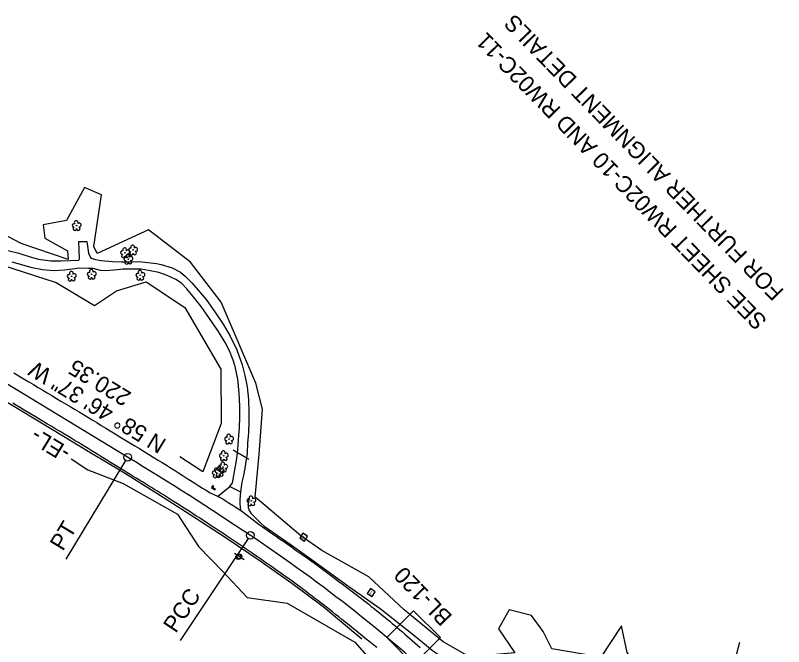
# Model space of a CAD drawing. Extents: x 473158 to 477500, y 500738 to 505114.
# Drawn here: x 474989 to 475741, y 502724 to 503341 of the extents above; entities that cross this region are included whole.
import ezdxf

# ---------------------------------------------------------------- set-up
doc = ezdxf.new("R2010")
doc.units = 0
for name, color, linetype in [('CTL Secondary Horizontal and Vertical CELL', 7, 'Continuous'), ('CTL Secondary Horizontal and Vertical Text', 7, 'Continuous'), ('CTL Sheet Notes CELL', 7, 'Continuous'), ('Exist Guardrail', 7, 'Continuous'), ('Exist Horizontal Alignment', 7, 'Continuous'), ('Exist Horizontal Alignment Direction Label', 7, 'Continuous'), ('Exist Other Culture Gate', 7, 'Continuous'), ('Exist Roads EOP', 7, 'Continuous'), ('Exist Roads EOP Other', 7, 'Continuous'), ('Exist Roads Soil', 7, 'Continuous'), ('Exist Structure Minor Head and End Wall', 7, 'Continuous'), ('Exist Utilities Other Pole CELL', 7, 'Continuous'), ('Exist Utilities Telephone Pedestal CELL', 7, 'Continuous'), ('Exist Utilities Telephone Pole CELL', 7, 'Continuous'), ('Exist Vegetation Tree CELL', 7, 'Continuous'), ('Exist Vegetation Woods Line', 7, 'Continuous')]:
    doc.layers.add(name, color=color, linetype=linetype)

msp = doc.modelspace()

# ---------------------------------------------------------------- linework, layer by layer
at = {"layer": 'CTL Secondary Horizontal and Vertical CELL'}
msp.add_line((475378.34, 502732.63), (475378.34, 502732.63), dxfattribs=at)
msp.add_lwpolyline([(475352.26, 502732.72), (475378.47, 502758.92), (475404.72, 502732.67), (475378.52, 502706.47)], close=True, dxfattribs=at)
at = {"layer": 'Exist Guardrail'}
for points in [[(475115.79, 502880.86), (475093.81, 502894.53), (475063.36, 502912.74), (475035.88, 502929.45), (475010.91, 502944.41), (474990.4, 502956.68), (474968.08, 502970.09), (474943.75, 502984.87), (474916.99, 503000.7), (474891.57, 503015.94), (474864.64, 503032.77), (474837.82, 503050.6), (474809.48, 503069.89), (474784.69, 503087.26), (474764.25, 503101.88), (474737.05, 503123.11), (474718.63, 503138.15), (474703.33, 503150.95), (474689.31, 503162.58), (474683.03, 503166.54), (474677.9, 503167.41)], [(475327.84, 502731.26), (475289.95, 502762.7), (475259.47, 502785.5), (475228.43, 502807.52), (475194.97, 502829.87), (475164.5, 502849.96), (475133.52, 502869.78), (475115.79, 502880.86)], [(475217.33, 502867.76), (475216.44, 502862.82), (475216.67, 502859.88), (475217.59, 502857.13), (475219.31, 502854.45), (475221.83, 502851.72), (475229.36, 502844.29), (475232.25, 502841.82), (475257.72, 502824.07), (475280.52, 502807.76), (475315.04, 502782.65), (475345.62, 502761.25), (475378.34, 502735.51), (475396.81, 502720.46), (475415.24, 502707), (475419.92, 502704.07), (475423.92, 502701.99), (475431.54, 502699.97), (475438.09, 502699.45), (475447.54, 502700.48), (475462.27, 502702.99), (475484.79, 502708.35), (475503.22, 502713.19)]]:
    msp.add_lwpolyline(points, dxfattribs=at)
at = {"layer": 'Exist Horizontal Alignment'}
for p, q in [((475098.63, 502909.13), (474910.19, 503023.36)), ((475096.69, 502905.93), (475038.25, 502809.53)), ((475216.71, 502829.51), (475150.03, 502729.7))]:
    msp.add_line(p, q, dxfattribs=at)
for centre in [(475098.63, 502909.13), (475218.79, 502832.63)]:
    msp.add_circle(centre, 3.75, dxfattribs=at)
for centre, radius, start, end in [((473422.15, 500143.44), 3234.14, 56.25321, 58.77708), ((474341.25, 501519.13), 1579.67, 47.05976, 56.25321)]:
    msp.add_arc(centre, radius, start, end, dxfattribs=at)
at = {"layer": 'Exist Other Culture Gate'}
msp.add_line((475217.28, 502907.02), (475201.99, 502915.99), dxfattribs=at)
at = {"layer": 'Exist Roads EOP'}
for points in [[(474987.32, 502991.6), (474990.65, 502989.58), (474994.12, 502987.49), (474997.91, 502985.21), (475002.02, 502982.76), (475006.44, 502980.12), (475011.01, 502977.41), (475015.54, 502974.71), (475020.03, 502972.03), (475024.48, 502969.37), (475028.91, 502966.72), (475033.35, 502964.06), (475037.79, 502961.4), (475042.25, 502958.74), (475046.68, 502956.08), (475051.08, 502953.44), (475055.43, 502950.81), (475059.75, 502948.2), (475064.05, 502945.58), (475068.39, 502942.95), (475072.76, 502940.29), (475077.17, 502937.62), (475081.65, 502934.9), (475086.27, 502932.09), (475091.01, 502929.22), (475095.87, 502926.26), (475100.75, 502923.3), (475105.51, 502920.4), (475110.15, 502917.56), (475114.68, 502914.78), (475119.14, 502912.05), (475123.56, 502909.34), (475127.94, 502906.64), (475132.28, 502903.97), (475136.53, 502901.35), (475140.62, 502898.81), (475144.55, 502896.34), (475148.32, 502893.95), (475152.09, 502891.56), (475156.01, 502889.06), (475160.08, 502886.47), (475164.31, 502883.77), (475168.36, 502881.2), (475171.91, 502878.99), (475174.95, 502877.13), (475179.54, 502874.43), (475182.3, 502872.88), (475187.13, 502870.72), (475191.66, 502868.39), (475194.11, 502866.87), (475196.95, 502864.99), (475201.9, 502861.84), (475203.85, 502860.64), (475208.93, 502857.47), (475213.05, 502854.51), (475215.96, 502852.2), (475220.03, 502848.88), (475224.63, 502845.43), (475227.48, 502843.34), (475230.27, 502841.31), (475233.01, 502839.35), (475235.7, 502837.47), (475238.42, 502835.58), (475241.27, 502833.6), (475244.25, 502831.55), (475247.37, 502829.42), (475250.45, 502827.31), (475253.33, 502825.32), (475256.03, 502823.44), (475258.53, 502821.68), (475261.03, 502819.92), (475263.69, 502818.04), (475266.52, 502816.04), (475269.52, 502813.92), (475272.58, 502811.76), (475275.57, 502809.64), (475278.5, 502807.55), (475281.36, 502805.51), (475284.15, 502803.5), (475286.85, 502801.53), (475289.46, 502799.59), (475291.98, 502797.7), (475294.52, 502795.78), (475297.17, 502793.77), (475299.93, 502791.69), (475302.8, 502789.52), (475305.72, 502787.32), (475308.62, 502785.14), (475311.49, 502782.99), (475314.35, 502780.86), (475317.13, 502778.78), (475319.78, 502776.77), (475322.3, 502774.85), (475324.69, 502772.99), (475327.05, 502771.15), (475329.48, 502769.25), (475331.97, 502767.29), (475334.52, 502765.27), (475337.12, 502763.21), (475339.74, 502761.13), (475342.38, 502759.03), (475345.04, 502756.9), (475347.68, 502754.78), (475350.25, 502752.7), (475352.77, 502750.66), (475355.22, 502748.65), (475357.64, 502746.64), (475360.09, 502744.59), (475362.55, 502742.49), (475365.02, 502740.36), (475367.49, 502738.21), (475369.93, 502736.09), (475372.34, 502733.99), (475374.72, 502731.91), (475377.14, 502729.81), (475379.67, 502727.64), (475382.29, 502725.41), (475385.02, 502723.12)], [(475342.53, 502722.84), (475339.47, 502725.33), (475336.39, 502727.82), (475333.41, 502730.24), (475330.53, 502732.58), (475327.74, 502734.83), (475325.01, 502737.04), (475322.3, 502739.22), (475319.6, 502741.38), (475316.91, 502743.53), (475314.17, 502745.72), (475311.31, 502748), (475308.33, 502750.39), (475305.22, 502752.88), (475302.09, 502755.37), (475299.04, 502757.79), (475296.08, 502760.13), (475293.2, 502762.38), (475290.37, 502764.59), (475287.55, 502766.77), (475284.73, 502768.92), (475281.93, 502771.06), (475279.14, 502773.17), (475276.38, 502775.26), (475273.64, 502777.34), (475270.92, 502779.4), (475268.31, 502781.37), (475263.68, 502784.83), (475259.62, 502787.78), (475255.06, 502791.06), (475252.52, 502792.87), (475249.89, 502794.73), (475247.25, 502796.6), (475244.6, 502798.48), (475241.95, 502800.35), (475239.29, 502802.22), (475236.62, 502804.09), (475233.94, 502805.96), (475231.24, 502807.82), (475228.54, 502809.68), (475225.83, 502811.54), (475223.11, 502813.41), (475220.38, 502815.27), (475217.61, 502817.16), (475214.79, 502819.09), (475211.91, 502821.07), (475208.98, 502823.09), (475206.03, 502825.11), (475203.12, 502827.1), (475200.24, 502829.04), (475197.41, 502830.95), (475194.56, 502832.85), (475191.64, 502834.79), (475188.65, 502836.77), (475185.59, 502838.79), (475182.45, 502840.85), (475179.19, 502842.98), (475175.83, 502845.17), (475172.36, 502847.42), (475168.87, 502849.68), (475165.43, 502851.91), (475162.05, 502854.09), (475158.72, 502856.23), (475155.43, 502858.34), (475152.17, 502860.43), (475148.94, 502862.5), (475145.74, 502864.55), (475142.59, 502866.56), (475139.52, 502868.52), (475136.53, 502870.41), (475133.62, 502872.25), (475130.75, 502874.06), (475127.85, 502875.87), (475124.93, 502877.68), (475121.99, 502879.48), (475119.03, 502881.29), (475116.07, 502883.1), (475113.09, 502884.92), (475110.11, 502886.74), (475107.1, 502888.57), (475104.07, 502890.43), (475101.02, 502892.31), (475097.93, 502894.22), (475094.82, 502896.16), (475091.67, 502898.12), (475088.48, 502900.1), (475085.25, 502902.1), (475082.02, 502904.1), (475078.82, 502906.08), (475075.63, 502908.04), (475072.47, 502909.99), (475069.32, 502911.93), (475066.17, 502913.86), (475063.01, 502915.79), (475059.85, 502917.72), (475056.7, 502919.64), (475053.57, 502921.55), (475050.48, 502923.43), (475047.41, 502925.3), (475044.2, 502927.25), (475040.67, 502929.37), (475036.83, 502931.68), (475032.67, 502934.17), (475028.42, 502936.71), (475024.32, 502939.17), (475020.36, 502941.55), (475016.54, 502943.84), (475012.78, 502946.11), (475008.98, 502948.39), (475005.15, 502950.68), (475001.29, 502952.99), (474997.44, 502955.28), (474993.65, 502957.54), (474989.91, 502959.76), (474986.24, 502961.95)]]:
    msp.add_lwpolyline(points, dxfattribs=at)
at = {"layer": 'Exist Roads EOP Other'}
msp.add_lwpolyline([(475186.67, 502870.84), (475191.74, 502875.05), (475198.74, 502880.37), (475204.5, 502877.64), (475208.93, 502875.37), (475208.43, 502867.73), (475208.54, 502863.42), (475208.67, 502860.65), (475209.1, 502857.83)], dxfattribs=at)
at = {"layer": 'Exist Roads Soil'}
for points in [[(474981.33, 503111.42), (474992.13, 503108.66), (475003.12, 503105.08), (475011.38, 503102.75), (475023.52, 503101.17), (475033.18, 503101.19), (475042.45, 503101.46), (475050.78, 503101.93), (475051.62, 503103.29), (475050.77, 503120.15), (475058.56, 503120.04), (475060.41, 503108.59), (475062.18, 503104.57), (475063.95, 503103.36), (475067.06, 503102.39), (475072.85, 503101.67), (475083.7, 503100.69), (475092.66, 503100.31), (475098.65, 503100.18), (475109.6, 503100.68), (475118.54, 503099.62), (475126.73, 503098.59), (475131.55, 503097.8), (475142.31, 503094.28), (475150.38, 503090.16), (475155.38, 503085.9), (475161.39, 503079.87), (475167.66, 503072.57), (475175.37, 503063.34), (475184.08, 503051.32), (475192.03, 503039.2), (475198.97, 503027.57), (475205.57, 503014.28), (475210.73, 502999.42), (475213.38, 502989.17), (475215.68, 502978.11), (475216.85, 502965.74), (475217.34, 502952.57), (475217.16, 502944.83)], [(475208.21, 502938), (475208.44, 502948.62), (475208.58, 502959.18), (475207.71, 502971.73), (475206.35, 502985.48), (475203.79, 502997.93), (475201.95, 503004.07), (475198.32, 503013.21), (475194.19, 503021.47), (475187.4, 503032.04), (475178.7, 503044.87), (475170.51, 503056.45), (475164.21, 503064.87), (475156.64, 503073.85), (475151.28, 503079.45), (475145.74, 503083.13), (475137.17, 503086.83), (475129.11, 503089.74), (475118.98, 503091.93), (475111.89, 503092.92), (475105.13, 503093.21), (475093.93, 503093.04), (475088.69, 503092.33), (475077.54, 503091.38), (475071.92, 503091.79), (475064.89, 503093.61), (475059.92, 503093.72), (475051.7, 503093.99), (475036.89, 503092.02), (475025.93, 503091.45), (475015.2, 503092.57), (475005.28, 503094.28), (474997.32, 503096.78), (474985.68, 503099.85)], [(475217.16, 502944.83), (475216.83, 502932.64), (475215.94, 502923.12), (475215.45, 502912.62), (475214.03, 502902.56), (475212.26, 502892.41), (475210.33, 502884.71), (475208.93, 502875.37)], [(475198.74, 502880.37), (475201.17, 502884), (475201.98, 502887.82), (475203.58, 502896.75), (475205.2, 502905.86), (475206.16, 502913.25), (475206.85, 502920.79), (475207.48, 502930.75), (475208.21, 502938)]]:
    msp.add_lwpolyline(points, dxfattribs=at)
at = {"layer": 'Exist Structure Minor Head and End Wall'}
for p, q in [((475181.99, 502881.61), (475182.7, 502881.17)), ((475184.04, 502877.11), (475184.53, 502877.79))]:
    msp.add_line(p, q, dxfattribs=at)
for points in [[(475181.99, 502881.61), (475180.7, 502879.52), (475184.04, 502877.11)], [(475182.7, 502881.17), (475181.81, 502879.74), (475184.53, 502877.79)]]:
    msp.add_lwpolyline(points, dxfattribs=at)
at = {"layer": 'Exist Utilities Other Pole CELL'}
msp.add_circle((475207.13, 502811.58), 2.46, dxfattribs=at)
at = {"layer": 'Exist Utilities Telephone Pedestal CELL'}
for p, q in [((475270.92, 502830.79), (475270.92, 502830.79)), ((475337.04, 502776.65), (475337.04, 502776.65))]:
    msp.add_line(p, q, dxfattribs=at)
for points in [[(475274.73, 502831.75), (475269.98, 502834.71), (475267.02, 502829.96), (475271.77, 502827), (475274.73, 502831.75)], [(475340.87, 502777.5), (475336.21, 502780.59), (475333.12, 502775.93), (475337.79, 502772.84), (475340.87, 502777.5)]]:
    msp.add_lwpolyline(points, dxfattribs=at)
at = {"layer": 'Exist Utilities Telephone Pole CELL'}
for p, q in [((475203.26, 502815.39), (475212.63, 502809)), ((475207.95, 502812.19), (475207.95, 502812.19))]:
    msp.add_line(p, q, dxfattribs=at)
msp.add_circle((475207.95, 502812.19), 2.41, dxfattribs=at)
at = {"layer": 'Exist Vegetation Tree CELL'}
for p, q in [((475048.69, 503135.65), (475048.69, 503135.65)), ((475096.03, 503109.2), (475096.03, 503109.2)), ((475103.97, 503111.83), (475103.97, 503111.83)), ((475099.37, 503102.9), (475099.37, 503102.9)), ((475043.85, 503086.15), (475043.85, 503086.15)), ((475063.41, 503088.04), (475063.41, 503088.04)), ((475111.03, 503087.07), (475111.03, 503087.07)), ((475197.92, 502926.9), (475197.92, 502926.9)), ((475192.7, 502910.56), (475192.7, 502910.56)), ((475188.75, 502895.24), (475188.75, 502895.24)), ((475192.09, 502899.5), (475192.09, 502899.5)), ((475185.78, 502893.79), (475185.78, 502893.79)), ((475219.68, 502866.43), (475219.68, 502866.43))]:
    msp.add_line(p, q, dxfattribs=at)
for centre in [(475048.69, 503135.65), (475096.03, 503109.2), (475103.97, 503111.83), (475099.37, 503102.9), (475043.85, 503086.15), (475063.41, 503088.04), (475111.03, 503087.07), (475197.92, 502926.9), (475192.7, 502910.56), (475188.75, 502895.24), (475192.09, 502899.5), (475185.78, 502893.79), (475219.68, 502866.43)]:
    msp.add_circle(centre, 0.326, dxfattribs=at)
for centre, radius, start, end in [((475046.09, 503135.81), 1.73, 62.66361, 279.3457), ((475048.31, 503138.53), 1.86, 330.16508, 219.71335), ((475051.24, 503136.24), 1.9, 257.1011, 134.19993), ((475046.99, 503132.53), 1.69, 111.56708, 6.23104), ((475050.36, 503132.75), 1.7, 181.28216, 74.55999), ((475095.65, 503112.07), 1.86, 330.16508, 219.71335), ((475101.36, 503111.98), 1.73, 62.66361, 279.3457), ((475103.58, 503114.7), 1.86, 330.16508, 219.71335), ((475106.52, 503112.42), 1.9, 257.1011, 134.19993), ((475093.43, 503109.35), 1.73, 62.66361, 279.3457), ((475094.33, 503106.08), 1.69, 111.56708, 6.23104), ((475097.71, 503106.3), 1.7, 181.28216, 74.55999), ((475098.98, 503105.77), 1.86, 330.16508, 219.71335), ((475098.58, 503109.79), 1.9, 257.1011, 134.19993), ((475102.26, 503108.71), 1.69, 111.56708, 6.23104), ((475105.64, 503108.93), 1.7, 181.28216, 74.55999), ((475096.76, 503103.05), 1.73, 62.66361, 279.3457), ((475097.67, 503099.78), 1.69, 111.56708, 6.23104), ((475101.04, 503100), 1.7, 181.28216, 74.55999), ((475101.92, 503103.49), 1.9, 257.1011, 134.19993), ((475043.46, 503089.02), 1.86, 330.16508, 219.71335), ((475063.03, 503090.91), 1.86, 330.16508, 219.71335), ((475065.96, 503088.63), 1.9, 257.1011, 134.19993), ((475110.65, 503089.94), 1.86, 330.16508, 219.71335), ((475041.24, 503086.3), 1.73, 62.66361, 279.3457), ((475042.15, 503083.03), 1.69, 111.56708, 6.23104), ((475045.52, 503083.25), 1.7, 181.28216, 74.55999), ((475046.4, 503086.74), 1.9, 257.1011, 134.19993), ((475060.81, 503088.19), 1.73, 62.66361, 279.3457), ((475061.71, 503084.92), 1.69, 111.56708, 6.23104), ((475065.09, 503085.14), 1.7, 181.28216, 74.55999), ((475108.43, 503087.22), 1.73, 62.66361, 279.3457), ((475109.33, 503083.95), 1.69, 111.56708, 6.23104), ((475112.71, 503084.17), 1.7, 181.28216, 74.55999), ((475113.58, 503087.65), 1.9, 257.1011, 134.19993), ((475195.31, 502927.05), 1.73, 62.66361, 279.3457), ((475196.21, 502923.78), 1.69, 111.56708, 6.23104), ((475197.53, 502929.77), 1.86, 330.16508, 219.71335), ((475199.59, 502924), 1.7, 181.28216, 74.55999), ((475200.46, 502927.49), 1.9, 257.1011, 134.19993), ((475190.1, 502910.71), 1.73, 62.66361, 279.3457), ((475192.32, 502913.43), 1.86, 330.16508, 219.71335), ((475195.25, 502911.15), 1.9, 257.1011, 134.19993), ((475191, 502907.44), 1.69, 111.56708, 6.23104), ((475191.71, 502902.38), 1.86, 330.16508, 219.71335), ((475194.37, 502907.66), 1.7, 181.28216, 74.55999), ((475183.17, 502893.94), 1.73, 62.66361, 279.3457), ((475185.39, 502896.66), 1.86, 330.16508, 219.71335), ((475186.14, 502895.39), 1.73, 62.66361, 279.3457), ((475188.36, 502898.11), 1.86, 330.16508, 219.71335), ((475188.33, 502894.38), 1.9, 257.1011, 134.19993), ((475189.49, 502899.66), 1.73, 62.66361, 279.3457), ((475190.39, 502896.38), 1.69, 111.56708, 6.23104), ((475191.29, 502895.83), 1.9, 257.1011, 134.19993), ((475193.77, 502896.6), 1.7, 181.28216, 74.55999), ((475194.64, 502900.09), 1.9, 257.1011, 134.19993), ((475184.07, 502890.67), 1.69, 111.56708, 6.23104), ((475187.04, 502892.12), 1.69, 111.56708, 6.23104), ((475187.45, 502890.89), 1.7, 181.28216, 74.55999), ((475190.42, 502892.34), 1.7, 181.28216, 74.55999), ((475217.07, 502866.58), 1.73, 62.66361, 279.3457), ((475217.97, 502863.31), 1.69, 111.56708, 6.23104), ((475219.29, 502869.3), 1.86, 330.16508, 219.71335), ((475221.35, 502863.53), 1.7, 181.28216, 74.55999), ((475222.22, 502867.02), 1.9, 257.1011, 134.19993)]:
    msp.add_arc(centre, radius, start, end, dxfattribs=at)
at = {"layer": 'Exist Vegetation Woods Line'}
for points in [[(475230.74, 502956.28), (475224.23, 502981.44), (475190.08, 503060.84), (475160.08, 503099.98), (475118.98, 503131.59), (475068.87, 503108.51), (475065.61, 503115.38), (475072.91, 503165.78), (475056.48, 503173.08), (475038.73, 503140.56), (475015.88, 503136.4), (475017.52, 503123.45), (475039.78, 503110.89), (475040.49, 503102.56), (474994.31, 503118.33), (474891.59, 503171.92), (474843.84, 503210.58), (474818.2, 503232.27)], [(474721.03, 503201.76), (474726.93, 503205.62), (474777.53, 503218.87), (474797.52, 503211.74), (474810.54, 503204.36), (474855.4, 503156.33), (474903.01, 503123.3), (474964.67, 503100.45), (475028.79, 503079.9), (475066.1, 503057.4), (475087.57, 503072.04), (475116.81, 503080.55), (475154.47, 503055.63), (475189.77, 502995.25), (475190.23, 502942), (475172.13, 502894.97), (475149.76, 502909.51)], [(475697.4, 502727.92), (475688.86, 502696.09), (475686, 502663.11), (475652.17, 502674.74), (475599.58, 502703.42), (475587.38, 502718.1), (475582.11, 502744.06), (475561.68, 502713.66), (475513.63, 502721.78), (475505.24, 502738.53), (475493.85, 502754.4), (475471.86, 502759.83), (475461.5, 502741.2), (475477.48, 502717.68), (475433.11, 502713.77), (475407.41, 502728.53), (475369.2, 502759.84), (475334.77, 502792.14), (475288.78, 502817.79), (475268.13, 502832.08), (475231.22, 502863.61), (475223.58, 502870.17), (475227.24, 502912), (475230.74, 502956.28)], [(475043.48, 502907.55), (475059.64, 502896.69), (475094.38, 502883.41)], [(475094.38, 502883.41), (475147.35, 502853.58), (475167.9, 502821.85), (475191.94, 502797.5), (475215.72, 502771.8), (475254.69, 502766.43), (475320.94, 502728.35), (475357.01, 502687.58), (475374.45, 502655.84), (475366.77, 502612.6), (475363.45, 502578.81), (475365.9, 502542.13), (475385.44, 502483.6), (475398.73, 502449.23)]]:
    msp.add_lwpolyline(points, dxfattribs=at)

# ---------------------------------------------------------------- texts
at = {"layer": 'CTL Secondary Horizontal and Vertical Text'}
msp.add_text('BL-120', height=16, rotation=133.87228, dxfattribs=at).set_placement((475417.26, 502753.71))
at = {"layer": 'CTL Sheet Notes CELL'}
for s, p in [('FOR FURTHER ALIGNMENT DETAILS', (475741.85, 503072.06)), ('SEE SHEET RW02C-10 AND RW02C-11', (475725.27, 503043.23))]:
    msp.add_text(s, height=16, rotation=134.27452, dxfattribs=at).set_placement(p)
at = {"layer": 'Exist Horizontal Alignment'}
for s, rotation, p in [('PT', 58.77708, (475035.25, 502816.57)), ('PCC', 56.25321, (475145.72, 502736.33))]:
    msp.add_text(s, height=16, rotation=rotation, dxfattribs=at).set_placement(p)
at = {"layer": 'Exist Horizontal Alignment Direction Label'}
for s, p in [('N 58%%d 46\' 37" W', (475137.55, 502925.6)), ('220.35', (475103.31, 502971.8)), ('-EL-', (475044.18, 502917.24))]:
    msp.add_text(s, height=16, rotation=148.77708, dxfattribs=at).set_placement(p)
at = {"layer": 'Exist Utilities Telephone Pedestal CELL'}
for rotation, p in [(148.12268, (475272.79, 502831.65)), (146.47866, (475338.93, 502777.46))]:
    msp.add_text('T', height=3.42, rotation=rotation, dxfattribs=at).set_placement(p)

doc.saveas('drawing.dxf')
